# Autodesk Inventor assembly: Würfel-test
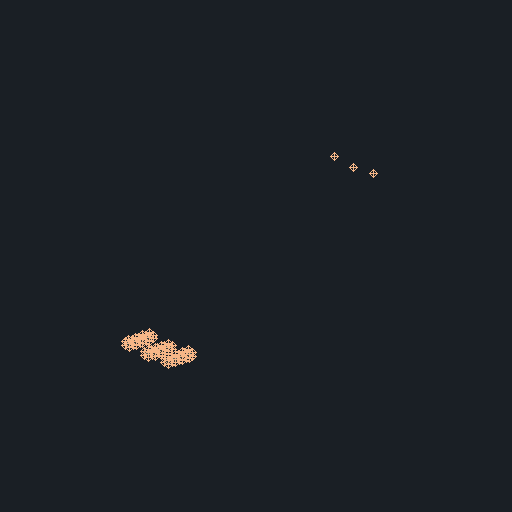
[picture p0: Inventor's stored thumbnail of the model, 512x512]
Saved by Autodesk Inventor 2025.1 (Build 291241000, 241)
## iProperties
Company: Ed. Züblin AG
Created: 2021-07
Part Number: Würfel-test
Material: Stahlbeton C30/37
Document SubType Name: Assembly
Designer: Eimannsmir
Mass: 44.4783 g
Surface Area: 94.0482 cm^2
Volume: 17.7913 cm^3
Density: 2.5 g/cm^3
z_Bereich: Tunnelbau
z_Direktion: Tief- und Tunnelbau
z_Konzerneinheit: Zentrale Technik
cpiComponentType: Attribut
cpiFitMatchkey: =<z_Matchkey>
z_Matchkey: =<z_Matchkey_010>_<z_Matchkey_020>_<z_Matchkey_030>_<z_Matchkey_040>_<z_Matchkey_050>_<z_Matchkey_060>_<z_Matchkey_070>_<z_Matchkey_080>_<z_Matchkey_090>_<z_Mat
z_Matchkey_010: xxxxx
z_Matchkey_020: 5DTUB
z_Matchkey_030: xxx
z_Matchkey_040: xxx
z_Matchkey_050: xxx
z_Matchkey_060: xxx
z_Matchkey_070: xxx
z_Matchkey_080: xxx
z_Matchkey_090: xxx
z_Matchkey_100: xxx
z_Matchkey_110: xxx
z_Matchkey_120: xxxxxxx
z_Matchkey_130: xxxx
z_Matchkey_140: xxxx
DocNumber: Würfel-test.iam
Folder: Übung\
VDS_Category: Konstruktion
Koordinate x - Ursprung: 10.0
Koordinate y - Ursprung: 0.0
Koordinate z - Ursprung: 0.0
Rotation - z-Achse: 0.0
Author: Eimannsmir
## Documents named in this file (2)
- C:\z_Vault\CAD\Übung\Würfel-test.iam
- C:\z_Vault\CAD\Übung\Würfel-1.iam
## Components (3 placed, 1 different names)
1. Würfel-1:1 [sub-assembly]
2. Würfel-1:2 [sub-assembly]
3. Würfel-1:3 [sub-assembly]
